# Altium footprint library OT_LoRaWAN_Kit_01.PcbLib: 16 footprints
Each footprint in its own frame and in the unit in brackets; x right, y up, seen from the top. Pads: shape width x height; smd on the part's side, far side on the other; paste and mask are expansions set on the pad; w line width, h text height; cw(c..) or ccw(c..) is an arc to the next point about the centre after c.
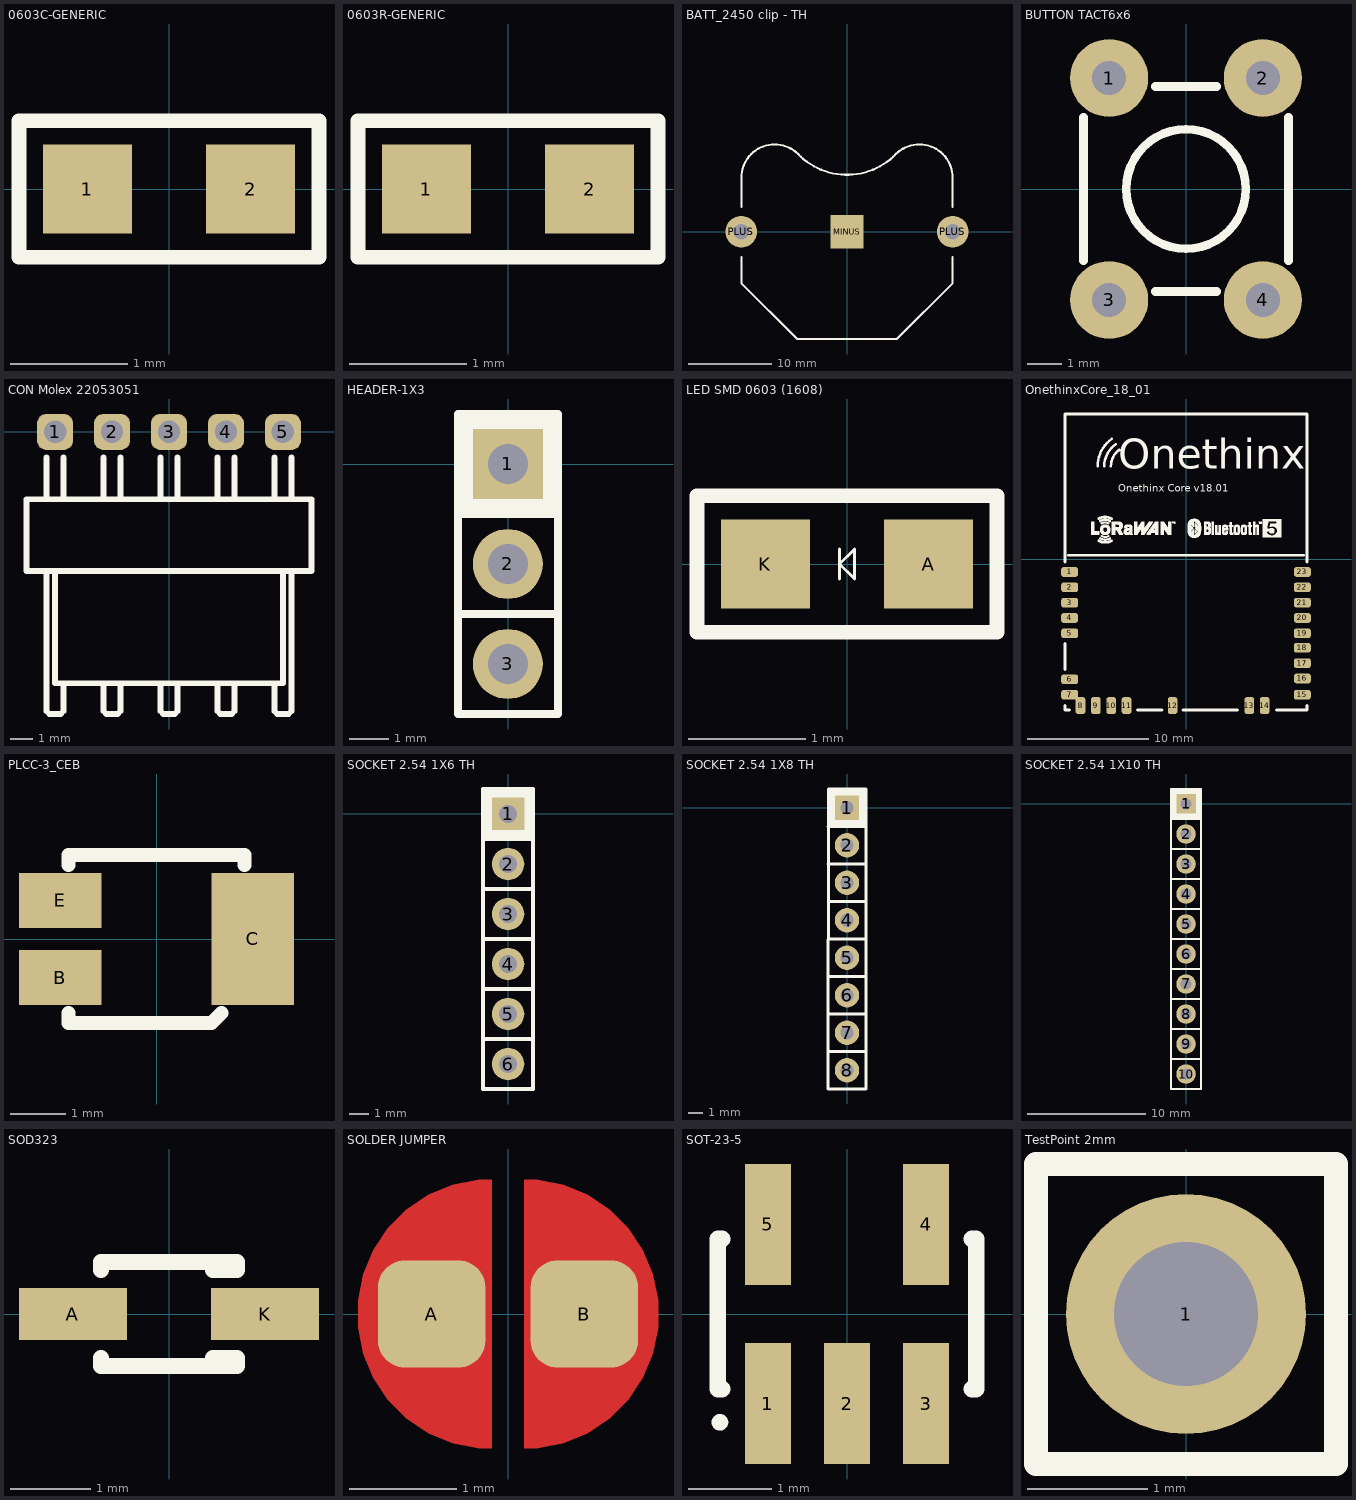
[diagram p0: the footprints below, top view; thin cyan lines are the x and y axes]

## 0603C-GENERIC [mil]
pads (2):
  rect 30x30 smd: 1(-27.56,0) 2(27.44,0)
Top Overlay:
  lines w5: -50.56,-23 50.44,-23 50.44,23 -50.56,23 -50.56,-23
3D body: height 19, standoff 18, extent -2.76,-4.33 1.57,4.33
3D body: height 18, standoff 0, extent -30.56,-14 30.44,14
3D body: height 19, standoff 0, extent 15.44,-15 31.44,15
3D body: height 19, standoff 0, extent -31.56,-15 -15.56,15

## 0603R-GENERIC [mil]
pads (2):
  rect 30x30 smd: 1(-27.5,0) 2(27.5,0)
Top Overlay:
  lines w5: -50.5,-23 -50.5,23 50.5,23 50.5,-23 -50.5,-23
3D body: height 18, standoff 0, extent -30.5,-14 30.5,14
3D body: height 19, standoff 18, extent -22.5,-13 22.5,13
3D body: height 19, standoff 0, extent 22.5,-15 31.5,15
3D body: height 19, standoff 0, extent -31.5,-15 -22.5,15
3D body: height 19.29, standoff 15, extent -2,-4.5 3,5.5

## BATT_2450 clip - TH [mm]
pads (3):
  rect 4x4 smd: MINUS(0,0)
  round 3.81 hole 1.85: PLUS(-12.7,0) PLUS(12.7,0)
Top Overlay:
  lines w0.254: -12.7,-3.025 -12.7,-6.2 -6,-12.9 6,-12.9 12.7,-6.2 12.7,-3.025 ; -12.7,3 -12.7,6.5 cw(c-8.7,6.5) -5.872,9.328 ; -5.892,9.349 ccw(c0,15) 5.892,9.349 ; 5.872,9.328 cw(c8.7,6.5) 12.7,6.5 12.7,3

## BUTTON TACT6x6 [mm]
pads (4):
  round 2.286 hole 1: 1(-2.25,3.25) 2(2.25,3.25) 3(-2.25,-3.25) 4(2.25,-3.25)
Top Overlay:
  circle w0.254: c0,0 r1.75
  lines w0.254: -3,-2.1 -3,2.1 ; -0.9,-3 0.9,-3 ; -0.9,3 0.9,3 ; 3,-2.1 3,2.1
3D body "Tact_6mm.stp": height 9.5, standoff -3.5, extent -3,-3.85 3,3.85

## CON Molex 22053051 [mm]
pads (5):
  rrect50% 1.6x1.6 hole 1: 1(-5.08,0) 2(-2.54,0) 3(0,0) 4(2.54,0) 5(5.08,0)
Top Overlay:
  lines w0.254: -5.461,-6.2 -5.461,-12.446 -5.334,-12.573 -4.826,-12.573 -4.699,-12.446 -4.699,-11.2 ; -5.461,-3 -5.461,-1.143 ; -5.08,-11.2 5.08,-11.2 ; -5.08,-11.176 -5.08,-6.2 ; -4.699,-3 -4.699,-1.143 ; -2.921,-11.2 -2.921,-12.446 -2.794,-12.573 -2.286,-12.573 -2.159,-12.446 -2.159,-11.2 ; -2.921,-3 -2.921,-1.143 ; -2.159,-3 -2.159,-1.143 ; -0.381,-11.2 -0.381,-12.446 -0.254,-12.573 0.254,-12.573 0.381,-12.446 0.381,-11.2 ; -0.381,-3 -0.381,-1.143 ; 0.381,-3 0.381,-1.143 ; 2.159,-11.2 2.159,-12.446 2.286,-12.573 2.794,-12.573 2.921,-12.446 2.921,-11.2 ; 2.159,-3 2.159,-1.143 ; 2.921,-3 2.921,-1.143 ; 4.699,-11.2 4.699,-12.446 4.826,-12.573 5.334,-12.573 5.461,-12.446 5.461,-6.2 ; 4.699,-3 4.699,-1.143 ; 5.08,-11.176 5.08,-6.2 ; 5.461,-3 5.461,-1.143 ; -6.35,-6.2 6.35,-6.2 6.35,-3 -6.35,-3 -6.35,-6.2

## HEADER-1X3 [mil]
pads (3):
  rect 70x70 hole 40: 1(-0.25,0)
  round 70 hole 40: 2(-0.25,-100) 3(-0.25,-200)
Top Overlay:
  rectangle: -50.25,-49.61 49.75,50
  lines w8: -50.25,-250 49.75,-250 ; -50.25,-150 49.75,-150 ; -50.25,-50 49.75,-50 ; -50.25,50 49.75,50 ; -50,-250 -50,50 ; 50,-250 50,50
3D body: height 101, standoff 100, extent -35.25,-35 35.25,35
3D body: height 100, standoff 0, extent -50.24,-249.99 49.76,-149.99
3D body: height 354.33, standoff -120, extent -15.24,-214.99 14.76,-184.99
3D body: height 100, standoff 0, extent -50.24,-149.99 49.76,-49.99
3D body: height 354.33, standoff -120, extent -15.24,-114.99 14.76,-84.99
3D body: height 100, standoff 0, extent -50.24,-49.99 49.76,50.01
3D body: height 354.33, standoff -120, extent -15.24,-14.99 14.76,15.01

## LED SMD 0603 (1608) [mil]
pads (2):
  rect 30x30 smd: A(27.5,0) K(-27.5,0)
Top Overlay:
  lines w1: -2.5,-5 -2.5,5 ; -2.5,0 2.5,5 2.5,-5 -2.5,0
  lines w5: -50.5,-23 -50.5,23 50.5,23 50.5,-23 -50.5,-23
3D body: height 10, standoff 0, extent -22.5,0 -22.5,0
3D body: height 20.47, standoff 19.68, extent -20,-5 -10,5
3D body: height 43.31, standoff 19.68, extent -22.5,-15 22.5,15
3D body: height 19.68, standoff 0, extent -30,-15 30,15

## OnethinxCore_18_01 [mm]
pads (23):
  rrect50% 1.4x0.8 smd: 1(-9.625,-1.07) 2(-9.625,-2.34) 3(-9.625,-3.61) 4(-9.625,-4.88) 5(-9.625,-6.15) 6(-9.625,-9.96) 7(-9.625,-11.23) 15(9.625,-11.23) 16(9.625,-9.882) 17(9.625,-8.612) 18(9.625,-7.342) 19(9.625,-6.15) 20(9.625,-4.88) 21(9.625,-3.61) 22(9.625,-2.34) 23(9.625,-1.07)
  rrect50% 0.8x1.4 smd: 8(-8.73,-12.125) 9(-7.46,-12.125) 10(-6.19,-12.125) 11(-4.92,-12.125) 12(-1.11,-12.125) 13(5.24,-12.125) 14(6.51,-12.125)
Top Overlay:
  drawing of 5793 lines, arcs and shapes, not listed
  text "Onethinx" at -5.625,6.625 h4.25
  text "Onethinx Core v18.01" at -5.625,5.375 h1.06
3D body: height 1.7, standoff 0, extent -8.5,-11 8.5,-0.5
3D body: height 0.25, standoff 0, extent 4.318,10.541 4.318,10.541

## PLCC-3_CEB [mm]
pads (3):
  rect 1.5x1 smd: B(-1.75,-0.7) E(-1.75,0.7)
  rect 1.5x2.4 smd: C(1.75,0)
Top Overlay:
  lines w0.254: -1.6,-1.346 -1.6,-1.527 1,-1.527 1.181,-1.346 ; -1.6,1.346 -1.6,1.527 1.6,1.527 1.6,1.346
3D body "LED_PLCC-4.STEP": height 1.95, standoff 0, extent -1.75,-1.4 1.75,1.4

## SOCKET 2.54 1X6 TH [mil]
pads (6):
  rect 65x65 hole 35.43: 1(0,0)
  round 65 hole 35.43: 2(0,-100) 3(0,-200) 4(0,-300) 5(0,-400) 6(0,-500)
Top Overlay:
  rectangle: -50,-49.62 50,50
  lines w8: -50,-450 50,-450 ; -50,-350 50,-350 ; -50,-250 50,-250 ; -50,-150 50,-150 ; -50,-50 50,-50 ; -50,-550 50,-550 50,50 -50,50 -50,-550
3D body: height 295.28, standoff 19.68, extent -50,-50 50,50
3D body: height 295.28, standoff 19.68, extent -50,-150 50,-50
3D body: height 157.48, standoff -118.11, extent -12.5,-112.5 12.5,-87.5
3D body: height 295.28, standoff 19.68, extent -50,-250 50,-150
3D body: height 295.28, standoff 19.68, extent -50,-450 50,-350
3D body: height 295.28, standoff 19.68, extent -50,-350 50,-250
3D body: height 295.28, standoff 19.68, extent -50,-550 50,-450
3D body: height 157.48, standoff -118.11, extent -12.5,-212.5 12.5,-187.5
3D body: height 157.48, standoff -118.11, extent -12.5,-312.5 12.5,-287.5
3D body: height 157.48, standoff -118.11, extent -12.5,-412.5 12.5,-387.5
3D body: height 157.48, standoff -118.11, extent -12.5,-512.5 12.5,-487.5
3D body: height 157.48, standoff -118.11, extent -12.5,-12.5 12.5,12.5

## SOCKET 2.54 1X8 TH [mil]
pads (8):
  rect 65x65 hole 35.43: 1(0,0)
  round 65 hole 35.43: 2(0,-100) 3(0,-200) 4(0,-300) 5(0,-400) 6(0,-500) 7(0,-600) 8(0,-700)
Top Overlay:
  rectangle: -50,-49.62 50,50
  lines w8: -50,-650 50,-650 ; -50,-550 50,-550 ; -50,-450 50,-450 ; -50,-350 50,-350 ; -50,-250 50,-250 ; -50,-150 50,-150 ; -50,-50 50,-50 ; -50,-750 -50,50 50,50 50,-750 -50,-750
3D body: height 295.28, standoff 19.68, extent -50,-50 50,50
3D body: height 295.28, standoff 19.68, extent -50,-150 50,-50
3D body: height 157.48, standoff -118.11, extent -12.5,-112.5 12.5,-87.5
3D body: height 295.28, standoff 19.68, extent -50,-250 50,-150
3D body: height 295.28, standoff 19.68, extent -50,-450 50,-350
3D body: height 295.28, standoff 19.68, extent -50,-350 50,-250
3D body: height 295.28, standoff 19.68, extent -50,-550 50,-450
3D body: height 157.48, standoff -118.11, extent -12.5,-212.5 12.5,-187.5
3D body: height 157.48, standoff -118.11, extent -12.5,-312.5 12.5,-287.5
3D body: height 157.48, standoff -118.11, extent -12.5,-412.5 12.5,-387.5
3D body: height 157.48, standoff -118.11, extent -12.5,-512.5 12.5,-487.5
3D body: height 157.48, standoff -118.11, extent -12.5,-12.5 12.5,12.5
3D body: height 157.48, standoff -118.11, extent -12.5,-712.5 12.5,-687.5
3D body: height 157.48, standoff -118.11, extent -12.5,-612.5 12.5,-587.5
3D body: height 295.28, standoff 19.68, extent -50,-750 50,-650
3D body: height 295.28, standoff 19.68, extent -50,-650 50,-550

## SOCKET 2.54 1X10 TH [mil]
pads (10):
  rect 65x65 hole 35.43: 1(0,0)
  round 65 hole 35.43: 2(0,-100) 3(0,-200) 4(0,-300) 5(0,-400) 6(0,-500) 7(0,-600) 8(0,-700) 9(0,-800) 10(0,-900)
Top Overlay:
  rectangle: -50,-49.62 50,50
  lines w8: -50,-850 50,-850 ; -50,-750 50,-750 ; -50,-650 50,-650 ; -50,-550 50,-550 ; -50,-450 50,-450 ; -50,-350 50,-350 ; -50,-250 50,-250 ; -50,-150 50,-150 ; -50,-50 50,-50 ; -50,-950 50,-950 50,50 -50,50 -50,-950
3D body: height 295.28, standoff 19.68, extent -50,-650 50,-550
3D body: height 295.28, standoff 19.68, extent -50,-850 50,-750
3D body: height 295.28, standoff 19.68, extent -50,-750 50,-650
3D body: height 295.28, standoff 19.68, extent -50,-950 50,-850
3D body: height 157.48, standoff -118.11, extent -12.5,-612.5 12.5,-587.5
3D body: height 157.48, standoff -118.11, extent -12.5,-712.5 12.5,-687.5
3D body: height 157.48, standoff -118.11, extent -12.5,-812.5 12.5,-787.5
3D body: height 157.48, standoff -118.11, extent -12.5,-912.5 12.5,-887.5
3D body: height 157.48, standoff -118.11, extent -12.5,-12.5 12.5,12.5
3D body: height 157.48, standoff -118.11, extent -12.5,-512.5 12.5,-487.5
3D body: height 157.48, standoff -118.11, extent -12.5,-412.5 12.5,-387.5
3D body: height 157.48, standoff -118.11, extent -12.5,-312.5 12.5,-287.5
3D body: height 157.48, standoff -118.11, extent -12.5,-212.5 12.5,-187.5
3D body: height 295.28, standoff 19.68, extent -50,-550 50,-450
3D body: height 295.28, standoff 19.68, extent -50,-350 50,-250
3D body: height 295.28, standoff 19.68, extent -50,-450 50,-350
3D body: height 295.28, standoff 19.68, extent -50,-250 50,-150
3D body: height 157.48, standoff -118.11, extent -12.5,-112.5 12.5,-87.5
3D body: height 295.28, standoff 19.68, extent -50,-150 50,-50
3D body: height 295.28, standoff 19.68, extent -50,-50 50,50

## SOD323 [mm]
pads (2):
  rect 1.35x0.65 smd: A(-1.2,0) K(1.2,0)
Top Overlay:
  lines w0.2: -0.85,-0.55 -0.85,-0.65 0.85,-0.65 0.85,-0.55 0.55,-0.55 0.55,-0.65 ; -0.85,0.55 -0.85,0.65 0.85,0.65 0.85,0.55 0.55,0.55 0.55,0.65
3D body "SOD323.STEP": height 0.9, standoff -0.09, extent -1.25,-0.625 1.25,0.625

## SOLDER JUMPER [mm]
pads (2):
  rrect50% 1x1 smd paste-10 mask+0: A(-0.711,0) B(0.711,0)
Top Layer:
  region: 0.152,-1.25 0.152,1.25 0.275,1.25 0.515,1.202 0.742,1.108 0.946,0.972 1.119,0.799 1.255,0.595 1.349,0.368 1.397,0.128 1.397,0.005 1.397,-0.005 1.397,-0.128 1.349,-0.368 1.255,-0.595 1.119,-0.799 0.946,-0.972 0.742,-1.108 0.515,-1.202 0.275,-1.25
  region: -0.152,1.25 -0.152,-1.25 -0.275,-1.25 -0.515,-1.202 -0.742,-1.108 -0.946,-0.972 -1.119,-0.799 -1.255,-0.595 -1.349,-0.368 -1.397,-0.128 -1.397,-0.005 -1.397,0.005 -1.397,0.128 -1.349,0.368 -1.255,0.595 -1.119,0.799 -0.946,0.972 -0.742,1.108 -0.515,1.202 -0.275,1.25

## SOT-23-5 [mm]
pads (5):
  rect 0.55x1.45 smd: 1(-0.95,-1.075) 2(0,-1.075) 3(0.95,-1.075) 4(0.95,1.075) 5(-0.95,1.075)
Top Overlay:
  circle w0.1: c-1.525,-1.3 r0.05
  lines w0.2: -1.5,-0.9 -1.55,-0.9 -1.55,0.9 -1.5,0.9 ; 1.5,-0.9 1.55,-0.9 1.55,0.9 1.5,0.9
3D body "SOT23-5.STEP": height 1.09, standoff -0.01, extent -1.45,-1.397 1.45,1.403

## TestPoint 2mm [mm]
pads (1):
  round 2 hole 1.2: 1(0,0)
Top Overlay:
  lines w0.203: -1.25,-1.25 1.25,-1.25 1.25,1.25 -1.25,1.25 -1.25,-1.25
